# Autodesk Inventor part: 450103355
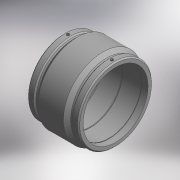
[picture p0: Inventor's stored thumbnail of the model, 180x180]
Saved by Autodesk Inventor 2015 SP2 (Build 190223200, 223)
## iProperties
Created: 2017-06
Part Number: 450103355
Material: Generic
Description: PLASSON COUPLER 355 PN25
Document SubType Name: Modeling
Designer: KIM
Mass: 10516.9 g
Surface Area: 7615.03 cm^2
Volume: 10516.9 cm^3
Density: 1 g/cm^3
Appearance: Default
Author: KIM
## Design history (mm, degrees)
derived "450103.ipt"
feature "Solid1::450103.ipt" dims "ScaleForDerivedMember" = 10
tag "TaggingFeature1"
body "Solid1"
other parameters: "d1" = 355 [user parameter], "d3" = 138 [user parameter], "d5" = 387 [user parameter], "d6" = 284 [user parameter], "d7" = 355 [user parameter], "d8" = 168 deg [user parameter], "d10" = 55.2 [user parameter], "d11" = 18.4 [user parameter], "d14" = 17.6296 [user parameter], "d15" = 138 [user parameter], "d16" = 138 [user parameter], "d17" = 351.45 [user parameter], "d18" = 355 [user parameter], "d19" = 3.52592 [user parameter], "d20" = 168 deg [user parameter], "d22" = 404.2 [user parameter], "d24" = 392.074 [user parameter], "d25" = 135 deg [user parameter], "d27" = 135 deg [user parameter], "d29" = 204 [user parameter], "d30" = 15 [user parameter], "d31" = 98 [user parameter], "d34" = 5 deg [user parameter], "d35" = 15 [user parameter], "d39" = 5 deg [user parameter], "d41" = 4 [user parameter], "d42" = 14 [user parameter], "d43" = 0 [user parameter], "d45" = 4 [user parameter], "d46" = 14 [user parameter], "d47" = 0 [user parameter], "d48" = 3 [user parameter], "d49" = 0 [user parameter], "d50" = 3 [user parameter], "d51" = 0 [user parameter], "d52" = 40.02 [user parameter], "d53" = 10.005 [user parameter], "d_" = 355 [user parameter], "L_1" = 138 [user parameter], "A_" = 204 [user parameter], "d_2" = 12 [user parameter]
